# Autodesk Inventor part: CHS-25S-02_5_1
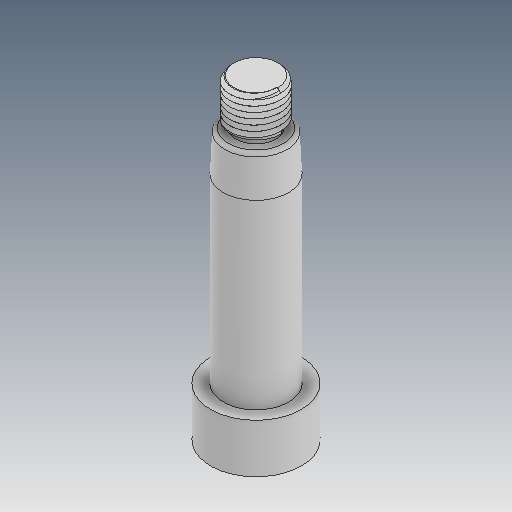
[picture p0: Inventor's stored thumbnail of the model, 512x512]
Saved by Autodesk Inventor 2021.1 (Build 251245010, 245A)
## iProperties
Created: 2019-05
Part Number: CHS-25S-02_5_1
Material: Ogólny
Document SubType Name: Modeling
Designer: user
Density: 1 g/cm^3
Appearance: Domyślna
Author: user
Revision Number: ÈÎºÎ
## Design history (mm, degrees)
feature "ÊäÈë1"
feature "ÊäÈë2"
node "Bryła1"
node "Bryła2"
